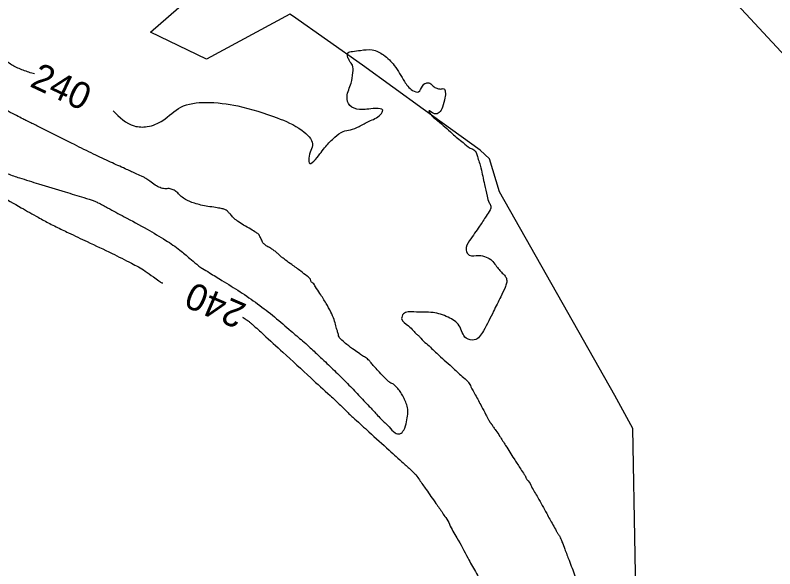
# Model space of a CAD drawing. Extents: x -478464 to -472469, y -1120963 to -1113785.
# Drawn here: x -476709.2 to -476595.5, y -1115480.5 to -1115397.7 of the extents above; entities that cross this region are included whole.
import ezdxf

# ---------------------------------------------------------------- set-up
doc = ezdxf.new("R2010")
doc.units = 0
for name, color, linetype in [('ObPÚ', 7, 'Continuous'), ('silnice', 7, 'Continuous'), ('Vrstevnice_hlavni', 7, 'Continuous'), ('Vrstevnice_popis', 7, 'Continuous'), ('Vrstevnice_vedlejsi', 7, 'Continuous')]:
    doc.layers.add(name, color=color, linetype=linetype)

msp = doc.modelspace()

# ---------------------------------------------------------------- linework, layer by layer
at = {"layer": 'ObPÚ'}
msp.add_lwpolyline([(-476616.07, -1115497.42), (-476616.77, -1115459.57), (-476619.44, -1115454.61), (-476636.69, -1115424.18), (-476638.21, -1115419.24), (-476639.59, -1115417.93), (-476648.12, -1115411.82), (-476657.2, -1115405.23), (-476667.65, -1115397.84), (-476668.05, -1115397.58), (-476680.55, -1115404.34), (-476688.91, -1115400.28), (-476683.54, -1115395.61), (-476662.2, -1115377.79), (-476669.9, -1115369.8), (-476680.76, -1115358.91), (-476694.9, -1115346.09), (-476702.33, -1115334.6), (-476708.16, -1115320.92), (-476704.55, -1115313.05), (-476707.22, -1115310.4), (-476710.61, -1115306.79)], dxfattribs=at)
at = {"layer": 'silnice'}
msp.add_lwpolyline([(-476200.543, -1116268.153), (-476239.965, -1116179.199), (-476260.934, -1116109.546), (-476288.613, -1116007.164), (-476289.451, -1115970.24), (-476274.354, -1115930.798), (-476261.922, -1115907.288), (-476366.595, -1115823.727), (-476390.845, -1115803.24), (-476425.665, -1115718.481), (-476494.983, -1115557.356), (-476524.795, -1115496.42), (-476580.823, -1115418.032), (-476641.911, -1115352.297), (-476741.891, -1115268.259), (-476824.194, -1115202.313), (-477005.33, -1115056.573), (-477039.82, -1115023.276), (-477040.729, -1115022.048)], dxfattribs=at)
at = {"layer": 'Vrstevnice_hlavni'}
for points in [[(-476706.244, -1115406.534), (-476707.96, -1115405.977), (-476708.765, -1115405.646), (-476709.518, -1115405.262), (-476710.217, -1115404.824), (-476711.27, -1115404.269), (-476712.675, -1115403.597), (-476714.434, -1115402.807), (-476715.989, -1115402.059), (-476717.342, -1115401.355), (-476718.492, -1115400.693), (-476719.238, -1115400.084), (-476719.582, -1115399.528), (-476719.523, -1115399.025), (-476719.448, -1115398.512), (-476719.358, -1115397.988), (-476719.252, -1115397.454), (-476719.997, -1115396.684), (-476721.591, -1115395.679), (-476724.035, -1115394.438), (-476725.867, -1115393.37), (-476727.085, -1115392.474), (-476727.69, -1115391.75), (-476728.521, -1115390.661), (-476729.577, -1115389.207), (-476730.859, -1115387.387), (-476731.765, -1115386.082), (-476732.296, -1115385.294), (-476732.452, -1115385.021), (-476732.923, -1115384.229), (-476733.709, -1115382.92), (-476734.811, -1115381.093), (-476735.566, -1115379.822), (-476735.975, -1115379.106), (-476736.037, -1115378.946), (-476736.15, -1115378.553), (-476736.314, -1115377.925), (-476736.529, -1115377.064), (-476736.693, -1115376.44), (-476736.804, -1115376.054), (-476736.863, -1115375.904), (-476736.982, -1115375.351), (-476737.16, -1115374.395), (-476737.397, -1115373.034), (-476737.307, -1115372.282), (-476736.89, -1115372.137), (-476736.146, -1115372.599), (-476735.855, -1115372.568), (-476736.017, -1115372.042), (-476736.632, -1115371.023), (-476737.082, -1115370.291), (-476737.367, -1115369.844), (-476737.488, -1115369.683), (-476737.612, -1115369.123), (-476737.741, -1115368.163), (-476737.873, -1115366.804), (-476738.07, -1115365.69), (-476738.33, -1115364.823), (-476738.654, -1115364.203), (-476739.078, -1115363.636), (-476739.6, -1115363.124), (-476740.222, -1115362.667), (-476740.66, -1115362.117), (-476740.914, -1115361.475), (-476740.986, -1115360.741), (-476741.152, -1115360.04), (-476741.413, -1115359.37), (-476741.77, -1115358.733), (-476740.52, -1115356.519), (-476737.663, -1115352.728), (-476733.201, -1115347.361), (-476731.168, -1115343.232), (-476731.564, -1115340.34), (-476734.39, -1115338.686), (-476736.463, -1115337.224), (-476737.782, -1115335.953), (-476738.347, -1115334.874), (-476738.355, -1115334.05), (-476737.808, -1115333.481), (-476736.704, -1115333.168), (-476736.602, -1115332.837), (-476737.501, -1115332.488), (-476739.402, -1115332.123), (-476740.763, -1115331.896), (-476741.585, -1115331.807), (-476741.868, -1115331.857), (-476742.175, -1115331.914), (-476742.506, -1115331.977), (-476742.861, -1115332.048), (-476743.46, -1115332.001), (-476744.303, -1115331.838), (-476745.392, -1115331.559), (-476746.072, -1115331.26), (-476746.343, -1115330.941), (-476746.207, -1115330.603), (-476746.075, -1115330.29), (-476745.949, -1115330.004)], [(-476694.514, -1115412.045), (-476691.345, -1115414.305), (-476689.393, -1115414.404), (-476687.074, -1115413.471), (-476684.386, -1115411.507), (-476680.639, -1115410.789), (-476675.832, -1115411.318), (-476669.965, -1115413.094), (-476666.242, -1115414.989), (-476664.663, -1115417.004), (-476665.227, -1115419.137), (-476665.089, -1115419.907), (-476664.248, -1115419.314), (-476662.704, -1115417.357), (-476661.315, -1115415.966), (-476660.082, -1115415.141), (-476659.004, -1115414.882), (-476657.715, -1115414.37), (-476656.214, -1115413.603), (-476654.502, -1115412.584), (-476654.173, -1115411.949), (-476655.227, -1115411.7), (-476657.665, -1115411.836), (-476659.089, -1115411.249), (-476659.5, -1115409.939), (-476658.898, -1115407.906), (-476658.635, -1115406.336), (-476658.712, -1115405.23), (-476659.128, -1115404.587), (-476659.376, -1115404.062), (-476659.454, -1115403.656), (-476659.363, -1115403.369), (-476658.713, -1115403.152), (-476657.505, -1115403.005), (-476655.737, -1115402.929), (-476654.049, -1115403.68), (-476652.439, -1115405.258), (-476650.909, -1115407.664), (-476649.699, -1115408.979), (-476648.811, -1115409.202), (-476648.243, -1115408.335), (-476647.687, -1115407.906), (-476647.144, -1115407.917), (-476646.613, -1115408.367), (-476646.085, -1115408.656), (-476645.559, -1115408.783), (-476645.036, -1115408.749), (-476644.807, -1115409.192), (-476644.871, -1115410.112), (-476645.229, -1115411.508), (-476645.747, -1115412.298), (-476646.426, -1115412.48), (-476647.265, -1115412.055), (-476647.104, -1115412.408), (-476645.942, -1115413.539), (-476643.78, -1115415.447), (-476642.16, -1115416.803), (-476641.083, -1115417.608), (-476640.548, -1115417.86), (-476640.014, -1115418.854), (-476639.481, -1115420.589), (-476638.949, -1115423.066), (-476638.54, -1115424.799), (-476638.253, -1115425.79), (-476638.09, -1115426.037), (-476638.013, -1115426.299), (-476638.023, -1115426.577), (-476638.119, -1115426.871), (-476638.676, -1115427.78), (-476639.692, -1115429.303), (-476641.169, -1115431.442), (-476641.68, -1115432.882), (-476641.226, -1115433.623), (-476639.806, -1115433.667), (-476638.674, -1115433.934), (-476637.83, -1115434.426), (-476637.273, -1115435.142), (-476636.759, -1115435.768), (-476636.288, -1115436.304), (-476635.858, -1115436.75), (-476635.644, -1115437.255), (-476635.645, -1115437.82), (-476635.862, -1115438.443), (-476636.512, -1115439.842), (-476637.596, -1115442.015), (-476639.114, -1115444.962), (-476640.476, -1115446.306), (-476641.681, -1115446.046), (-476642.729, -1115444.182), (-476644.383, -1115442.907), (-476646.642, -1115442.22), (-476649.507, -1115442.122), (-476651.073, -1115442.418), (-476651.342, -1115443.108), (-476650.314, -1115444.192), (-476649.587, -1115444.95), (-476649.162, -1115445.383)], [(-476717.286, -1115421.538), (-476717.213, -1115421.575), (-476716.913, -1115421.725), (-476716.385, -1115421.989), (-476715.629, -1115422.367), (-476714.019, -1115423.251), (-476711.555, -1115424.642), (-476708.236, -1115426.539), (-476705.712, -1115427.96), (-476703.983, -1115428.907), (-476703.047, -1115429.378), (-476701.182, -1115430.278), (-476698.387, -1115431.607), (-476694.663, -1115433.365), (-476691.771, -1115434.829), (-476689.711, -1115436), (-476688.482, -1115436.876), (-476687.644, -1115437.463), (-476687.195, -1115437.758), (-476687.077, -1115437.769)], [(-476675.172, -1115442.891), (-476674.626, -1115443.23), (-476674.326, -1115443.444), (-476673.998, -1115443.703), (-476673.643, -1115444.006), (-476672.012, -1115445.487), (-476669.106, -1115448.147), (-476664.923, -1115451.985), (-476662.048, -1115454.626), (-476660.479, -1115456.072), (-476660.217, -1115456.321), (-476659.967, -1115456.568), (-476659.729, -1115456.815), (-476659.502, -1115457.059), (-476658.339, -1115458.137), (-476656.24, -1115460.049), (-476653.205, -1115462.795), (-476651.104, -1115464.702), (-476649.939, -1115465.77), (-476649.71, -1115466), (-476649.538, -1115466.17), (-476649.425, -1115466.28), (-476649.37, -1115466.33), (-476649.316, -1115466.382), (-476649.261, -1115466.437), (-476649.207, -1115466.495), (-476648.681, -1115467.234), (-476647.683, -1115468.656), (-476646.214, -1115470.761), (-476645.234, -1115472.165), (-476644.744, -1115472.867), (-476644.743, -1115472.868), (-476644.742, -1115472.869), (-476644.741, -1115472.87), (-476644.189, -1115473.878), (-476643.085, -1115475.892), (-476641.429, -1115478.913), (-476640.313, -1115480.954), (-476639.736, -1115482.014), (-476639.7, -1115482.095), (-476639.658, -1115482.232), (-476639.61, -1115482.426), (-476639.555, -1115482.676), (-476639.518, -1115482.842), (-476639.5, -1115482.925), (-476639.501, -1115482.924), (-476639.378, -1115483.565), (-476639.133, -1115484.846), (-476638.766, -1115486.769), (-476638.404, -1115488.387), (-476638.048, -1115489.699), (-476637.698, -1115490.706), (-476637.354, -1115491.828), (-476637.017, -1115493.063), (-476636.686, -1115494.413), (-476636.484, -1115495.376), (-476636.411, -1115495.954), (-476636.467, -1115496.145), (-476636.546, -1115496.498), (-476636.648, -1115497.014), (-476636.772, -1115497.691), (-476636.911, -1115498.298), (-476637.064, -1115498.836), (-476637.232, -1115499.305), (-476637.332, -1115499.88), (-476637.364, -1115500.562), (-476637.328, -1115501.351), (-476637.305, -1115501.916), (-476637.295, -1115502.255), (-476637.299, -1115502.369), (-476637.302, -1115502.476), (-476637.305, -1115502.575), (-476637.308, -1115502.666), (-476637.314, -1115502.785), (-476637.323, -1115502.931), (-476637.335, -1115503.105), (-476637.185, -1115503.279), (-476636.871, -1115503.453), (-476636.395, -1115503.627), (-476635.985, -1115503.7), (-476635.641, -1115503.673), (-476635.364, -1115503.545), (-476635.163, -1115503.629), (-476635.036, -1115503.926), (-476634.985, -1115504.435), (-476634.924, -1115505.348), (-476634.853, -1115506.665), (-476634.773, -1115508.386), (-476634.73, -1115509.857), (-476634.725, -1115511.078), (-476634.757, -1115512.048), (-476634.794, -1115512.909), (-476634.835, -1115513.661), (-476634.88, -1115514.304), (-476634.986, -1115514.959), (-476635.152, -1115515.626)], [(-476649.162, -1115445.383), (-476649.04, -1115445.49), (-476648.941, -1115445.572), (-476648.865, -1115445.628), (-476648.813, -1115445.658), (-476648.733, -1115445.739), (-476648.624, -1115445.87), (-476648.485, -1115446.051), (-476647.64, -1115446.857), (-476646.086, -1115448.29), (-476643.825, -1115450.347), (-476642.282, -1115451.76), (-476641.459, -1115452.527), (-476641.355, -1115452.649), (-476640.975, -1115453.309), (-476640.32, -1115454.508), (-476639.39, -1115456.245), (-476638.725, -1115457.487), (-476638.325, -1115458.232), (-476638.189, -1115458.482), (-476638.072, -1115458.678), (-476637.972, -1115458.818), (-476637.89, -1115458.904), (-476637.818, -1115458.998), (-476637.755, -1115459.099), (-476637.701, -1115459.209), (-476637.598, -1115459.369), (-476637.444, -1115459.58), (-476637.241, -1115459.842), (-476636.687, -1115460.676), (-476635.784, -1115462.084), (-476634.529, -1115464.064), (-476633.647, -1115465.448), (-476633.135, -1115466.236), (-476632.994, -1115466.428), (-476632.881, -1115466.609), (-476632.795, -1115466.779), (-476632.737, -1115466.94), (-476632.656, -1115467.089), (-476632.553, -1115467.228), (-476632.427, -1115467.356), (-476631.9, -1115468.24), (-476630.973, -1115469.88), (-476629.645, -1115472.275), (-476628.725, -1115473.931), (-476628.212, -1115474.846), (-476628.107, -1115475.022), (-476628.006, -1115475.185), (-476627.909, -1115475.337), (-476627.816, -1115475.477), (-476627.693, -1115475.718), (-476627.539, -1115476.06), (-476627.355, -1115476.503), (-476626.941, -1115477.57), (-476626.298, -1115479.261), (-476625.426, -1115481.577), (-476624.826, -1115483.283), (-476624.499, -1115484.379), (-476624.444, -1115484.865), (-476624.364, -1115485.358), (-476624.256, -1115485.859), (-476624.123, -1115486.367), (-476623.9, -1115487.607), (-476623.587, -1115489.58), (-476623.185, -1115492.284), (-476622.903, -1115494.208), (-476622.739, -1115495.352), (-476622.695, -1115495.716), (-476622.601, -1115496.605), (-476622.457, -1115498.019), (-476622.264, -1115499.957), (-476622.111, -1115501.417), (-476622, -1115502.399), (-476621.93, -1115502.903), (-476621.882, -1115503.325), (-476621.857, -1115503.666), (-476621.854, -1115503.924), (-476621.783, -1115505.089), (-476621.644, -1115507.16), (-476621.437, -1115510.137), (-476621.299, -1115512.128), (-476621.23, -1115513.132), (-476621.229, -1115513.166)]]:
    msp.add_spline(points, degree=3, dxfattribs=at)
at = {"layer": 'Vrstevnice_vedlejsi'}
for points in [[(-476782.237, -1115320.123), (-476781.894, -1115320.658), (-476781.575, -1115321.206), (-476781.278, -1115321.766), (-476781.004, -1115322.338), (-476780.519, -1115323.233), (-476779.823, -1115324.45), (-476778.917, -1115325.991), (-476778.088, -1115327.415), (-476777.337, -1115328.722), (-476776.664, -1115329.912), (-476776.033, -1115330.843), (-476775.445, -1115331.514), (-476774.901, -1115331.926), (-476774.298, -1115332.797), (-476773.638, -1115334.125), (-476772.919, -1115335.911), (-476772.483, -1115337.259), (-476772.327, -1115338.168), (-476772.453, -1115338.639), (-476772.442, -1115339.19), (-476772.295, -1115339.823), (-476772.01, -1115340.536), (-476771.63, -1115341.381), (-476771.154, -1115342.357), (-476770.581, -1115343.464), (-476769.729, -1115345.262), (-476768.597, -1115347.752), (-476767.186, -1115350.932), (-476765.737, -1115354.067), (-476764.251, -1115357.156), (-476762.728, -1115360.2), (-476761.525, -1115362.664), (-476760.643, -1115364.548), (-476760.08, -1115365.851), (-476759.252, -1115367.612), (-476758.157, -1115369.831), (-476756.797, -1115372.509), (-476755.717, -1115374.638), (-476754.918, -1115376.22), (-476754.4, -1115377.253), (-476753.686, -1115378.773), (-476752.779, -1115380.777), (-476751.676, -1115383.267), (-476750.604, -1115385.569), (-476749.564, -1115387.683), (-476748.555, -1115389.609), (-476747.753, -1115391.107), (-476747.157, -1115392.176), (-476746.769, -1115392.816), (-476745.549, -1115394.316), (-476743.499, -1115396.676), (-476740.618, -1115399.896), (-476738.554, -1115402.201), (-476737.309, -1115403.591), (-476736.881, -1115404.066), (-476736.474, -1115404.475), (-476736.086, -1115404.817), (-476735.719, -1115405.094), (-476734.627, -1115406.069), (-476732.811, -1115407.743), (-476730.271, -1115410.116), (-476728.369, -1115411.818), (-476727.105, -1115412.85), (-476726.48, -1115413.21), (-476724.474, -1115414.254), (-476721.088, -1115415.982), (-476716.321, -1115418.392), (-476712.928, -1115420.107), (-476710.91, -1115421.125), (-476710.266, -1115421.447), (-476708.515, -1115422.06), (-476705.659, -1115422.963), (-476701.696, -1115424.157), (-476698.897, -1115425.025), (-476697.26, -1115425.566), (-476696.787, -1115425.782), (-476695.322, -1115426.55), (-476692.866, -1115427.871), (-476689.419, -1115429.745), (-476686.633, -1115431.41), (-476684.509, -1115432.866), (-476683.045, -1115434.113), (-476681.996, -1115434.986), (-476681.361, -1115435.485), (-476681.14, -1115435.61), (-476680.092, -1115436.253), (-476678.218, -1115437.413), (-476675.517, -1115439.092), (-476672.896, -1115440.911), (-476670.354, -1115442.871), (-476667.892, -1115444.973), (-476666.18, -1115446.439), (-476665.218, -1115447.269), (-476665.006, -1115447.464), (-476664.259, -1115448.17), (-476662.978, -1115449.387)], [(-476692.696, -1115420.715), (-476694.882, -1115419.718), (-476697.418, -1115418.513), (-476700.305, -1115417.098), (-476703.542, -1115415.474), (-476705.904, -1115414.291), (-476707.393, -1115413.548), (-476708.006, -1115413.245), (-476708.94, -1115412.765), (-476710.195, -1115412.109), (-476711.769, -1115411.277), (-476713.026, -1115410.593), (-476713.964, -1115410.057), (-476714.584, -1115409.67), (-476715.44, -1115409.145), (-476716.532, -1115408.483), (-476717.86, -1115407.685), (-476719.339, -1115406.838), (-476720.967, -1115405.943), (-476722.746, -1115405), (-476724.111, -1115404.266), (-476725.062, -1115403.741), (-476725.598, -1115403.425), (-476726.214, -1115403.111), (-476726.911, -1115402.798), (-476727.686, -1115402.486), (-476728.511, -1115401.948), (-476729.385, -1115401.185), (-476730.308, -1115400.195), (-476731.11, -1115399.36), (-476731.791, -1115398.678), (-476732.351, -1115398.151), (-476733.037, -1115397.46), (-476733.849, -1115396.605), (-476734.787, -1115395.585), (-476735.519, -1115394.786), (-476736.046, -1115394.208), (-476736.367, -1115393.85), (-476736.785, -1115393.311), (-476737.301, -1115392.59), (-476737.915, -1115391.688), (-476738.479, -1115390.88), (-476738.994, -1115390.167), (-476739.46, -1115389.548), (-476739.969, -1115388.839), (-476740.521, -1115388.04), (-476741.116, -1115387.15), (-476741.635, -1115386.268), (-476742.077, -1115385.393), (-476742.442, -1115384.525), (-476742.804, -1115383.666), (-476743.162, -1115382.817), (-476743.516, -1115381.976), (-476743.953, -1115380.785), (-476744.471, -1115379.244), (-476745.072, -1115377.352), (-476745.543, -1115375.832), (-476745.886, -1115374.684), (-476746.1, -1115373.907), (-476746.359, -1115373.068), (-476746.662, -1115372.167), (-476747.011, -1115371.204), (-476747.337, -1115370.311), (-476747.641, -1115369.486), (-476747.923, -1115368.731), (-476748.294, -1115367.873), (-476748.753, -1115366.912), (-476749.302, -1115365.848), (-476749.736, -1115364.822), (-476750.055, -1115363.834), (-476750.26, -1115362.883), (-476750.464, -1115362.104), (-476750.666, -1115361.495), (-476750.868, -1115361.057), (-476751.062, -1115360.642), (-476751.248, -1115360.25), (-476751.427, -1115359.881), (-476751.825, -1115359.097), (-476752.443, -1115357.899), (-476753.281, -1115356.286), (-476754.152, -1115354.57), (-476755.055, -1115352.753), (-476755.992, -1115350.832), (-476756.788, -1115349.188), (-476757.443, -1115347.818), (-476757.957, -1115346.723), (-476758.618, -1115345.368), (-476759.425, -1115343.752), (-476760.38, -1115341.875), (-476760.999, -1115340.59), (-476761.283, -1115339.895), (-476761.231, -1115339.792), (-476761.173, -1115339.655), (-476761.111, -1115339.485), (-476761.043, -1115339.281), (-476761.089, -1115339.081), (-476761.248, -1115338.885)], [(-476662.978, -1115449.387), (-476661.162, -1115451.115), (-476659.428, -1115452.833), (-476657.775, -1115454.539), (-476656.203, -1115456.234), (-476655.091, -1115457.422), (-476654.44, -1115458.103), (-476654.248, -1115458.277), (-476653.83, -1115458.682), (-476653.188, -1115459.318), (-476652.32, -1115460.185), (-476651.602, -1115460.342), (-476651.034, -1115459.79), (-476650.616, -1115458.529), (-476650.426, -1115457.411), (-476650.465, -1115456.437), (-476650.734, -1115455.606), (-476651.064, -1115454.853), (-476651.456, -1115454.179), (-476651.91, -1115453.583), (-476652.314, -1115453.147), (-476652.667, -1115452.871), (-476652.971, -1115452.754), (-476653.438, -1115452.391), (-476654.067, -1115451.782), (-476654.86, -1115450.927), (-476655.478, -1115450.245), (-476655.922, -1115449.736), (-476656.193, -1115449.4), (-476656.471, -1115449.126), (-476656.758, -1115448.916), (-476657.052, -1115448.768), (-476657.611, -1115448.399), (-476658.436, -1115447.809), (-476659.525, -1115446.999), (-476660.283, -1115446.343), (-476660.709, -1115445.841), (-476660.803, -1115445.493), (-476660.957, -1115444.947), (-476661.171, -1115444.203), (-476661.444, -1115443.26), (-476661.933, -1115442.141), (-476662.639, -1115440.846), (-476663.561, -1115439.375), (-476664.221, -1115438.364), (-476664.618, -1115437.813), (-476664.752, -1115437.722), (-476664.86, -1115437.596), (-476664.943, -1115437.434), (-476665, -1115437.237), (-476665.492, -1115436.771), (-476666.419, -1115436.037), (-476667.78, -1115435.035), (-476668.702, -1115434.357), (-476669.185, -1115434.005), (-476669.229, -1115433.978), (-476669.39, -1115433.837), (-476669.67, -1115433.583), (-476670.069, -1115433.216), (-476670.505, -1115432.879), (-476670.978, -1115432.571), (-476671.488, -1115432.293), (-476671.875, -1115432.002), (-476672.139, -1115431.697), (-476672.28, -1115431.379), (-476672.413, -1115431.092), (-476672.539, -1115430.834), (-476672.658, -1115430.608), (-476673.107, -1115430.246), (-476673.887, -1115429.751), (-476674.998, -1115429.121), (-476675.882, -1115428.538), (-476676.537, -1115428.001), (-476676.965, -1115427.511), (-476677.317, -1115427.145), (-476677.594, -1115426.903), (-476677.795, -1115426.786), (-476678.319, -1115426.654), (-476679.165, -1115426.506), (-476680.332, -1115426.344), (-476681.381, -1115426.133), (-476682.309, -1115425.874), (-476683.118, -1115425.567), (-476683.832, -1115425.184), (-476684.45, -1115424.726), (-476684.974, -1115424.193), (-476685.537, -1115423.844), (-476686.14, -1115423.68), (-476686.782, -1115423.702), (-476687.474, -1115423.526), (-476688.215, -1115423.152), (-476689.005, -1115422.58), (-476689.612, -1115422.166), (-476690.034, -1115421.909), (-476690.272, -1115421.81), (-476691.16, -1115421.412), (-476692.696, -1115420.715)]]:
    msp.add_spline(points, degree=3, dxfattribs=at)

# ---------------------------------------------------------------- texts
at = {"layer": 'Vrstevnice_popis'}
for rotation, p in [(334.84831, (-476708.47, -1115407.691)), (156.68695, (-476672.98, -1115441.651))]:
    msp.add_text(' 240 ', height=4, rotation=rotation, dxfattribs=at).set_placement(p)

doc.saveas('drawing.dxf')
